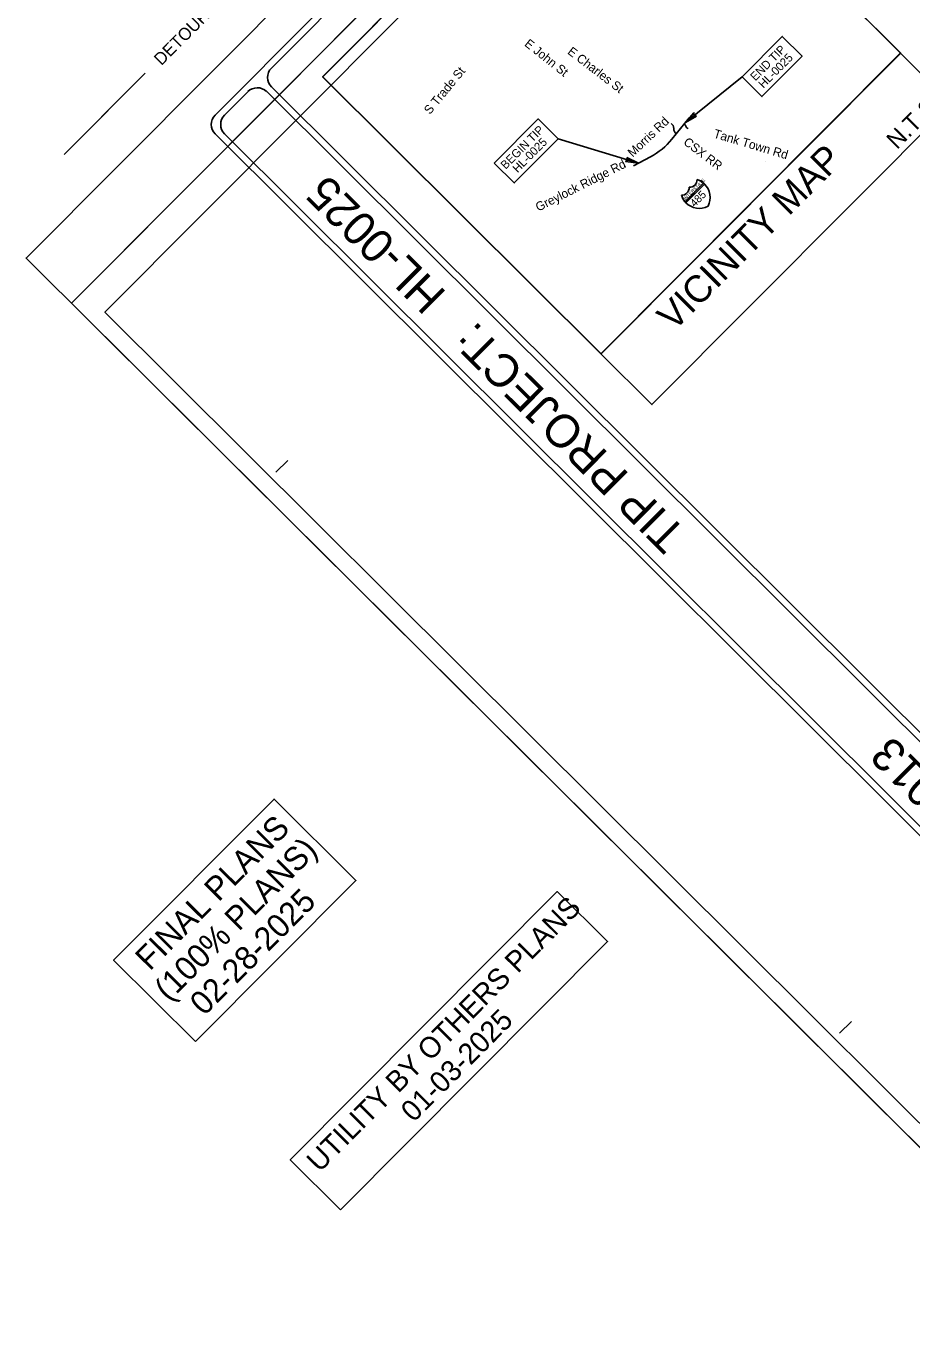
# Model space of a CAD drawing. Extents: x 1484850 to 1495577, y 495475 to 506245.
# Drawn here: x 1484916 to 1486921, y 495475 to 498431 of the extents above; entities that cross this region are included whole.
import ezdxf

# ---------------------------------------------------------------- set-up
doc = ezdxf.new("R2010")
doc.units = 0
for name, color, linetype in [('Cell Prop Down Guy _B', 7, 'Continuous'), ('Default', 7, 'Continuous'), ('Exist Utilities Gas UG Line SUE LOS B', 7, 'Continuous'), ('Exist Utilities Sanitary Sewer Manhole CELL', 7, 'Continuous'), ('Exist Utilities TV Pedestal CELL', 7, 'Continuous'), ('Exist Utilities TV UG Cable SUE LOS C', 7, 'Continuous'), ('Exist Utilities Water Meter CELL', 7, 'Continuous'), ('Exist Utilities Water UG Line SUE LOS C', 7, 'Continuous'), ('P Pole (Pow Co) CELL', 7, 'Continuous'), ('Prop Conduit _B', 7, 'Continuous'), ('Prop Guy Wire', 7, 'Continuous'), ('Prop UG Pow Cables', 7, 'Continuous')]:
    doc.layers.add(name, color=color, linetype=linetype)

msp = doc.modelspace()

# ---------------------------------------------------------------- linework, layer by layer
at = {"layer": 'Cell Prop Down Guy _B'}
for q in [(1488584.2, 501383.6), (1487357.7, 495475.3)]:
    msp.add_line((1485019.4, 497803.9), q, dxfattribs=at)
msp.add_lwpolyline([(1485019.4, 497803.9), (1488584.2, 501383.6), (1490922.5, 499055), (1487357.7, 495475.3)], close=True, dxfattribs=at)
at = {"layer": 'Default'}
for p, q in [((1485186.1, 498325), (1485018, 498156.3)), ((1485170.6, 498309.5), (1485002.6, 498140.8))]:
    msp.add_line(p, q, dxfattribs=at)
at = {"layer": 'Exist Utilities Gas UG Line SUE LOS B'}
for p, q in [((1486377.6, 498175.4), (1486416.8, 498224)), ((1486381.8, 498199.3), (1486381.8, 498199.9)), ((1486409.3, 498205.1), (1486410, 498203.6)), ((1486290.9, 498115.2), (1486329.2, 498135.5))]:
    msp.add_line(p, q, dxfattribs=at)
for centre, radius, start, end in [((1486366.2, 498199.2), 15.6, 2.8235, 50.7272), ((1486398.2, 498199.4), 16.4, 180.3319, 227.5042), ((1486397.2, 498200.3), 13, 21.6462, 49.5197), ((1486421.3, 498209.8), 12.9, 208.8639, 235.4773), ((1486256.3, 498273.1), 155.7, 297.895, 321.1156)]:
    msp.add_arc(centre, radius, start, end, dxfattribs=at)
at = {"layer": 'Exist Utilities Sanitary Sewer Manhole CELL'}
for points in [[(1486433.5, 498227.4), (1486408.1, 498213.2), (1486427.3, 498235.4), (1486427.7, 498229.1)], [(1486275.8, 498134.2), (1486301.8, 498121), (1486272.7, 498124.6), (1486277.7, 498128.4)]]:
    msp.add_lwpolyline(points, close=True, dxfattribs=at)
at = {"layer": 'Exist Utilities TV Pedestal CELL'}
for p, q in [((1486589.6, 498124.1), (1486589.5, 498124)), ((1486589.6, 498124.1), (1486589.5, 498124)), ((1486589.5, 498124), (1486589.6, 498124.1)), ((1486449.2, 498076), (1486407.2, 498033.8)), ((1486407.3, 498033.9), (1486449.2, 498076)), ((1486451.5, 498073.9), (1486409.3, 498031.5)), ((1486409.3, 498031.5), (1486451.5, 498073.9))]:
    msp.add_line(p, q, dxfattribs=at)
for centre, radius, start, end in [((1486417.6, 498083.3), 16.8, 266.268, 2.8189), ((1486421.9, 498043.6), 42.4, 49.933, 72.9434), ((1486399.7, 498065.4), 16.8, 267.4184, 3.9692), ((1486421.9, 498043.6), 42.4, 45.6712, 49.9313), ((1486421.9, 498043.6), 42.4, 332.3215, 45.6591), ((1486439.5, 498061.2), 42.4, 197.294, 220.283), ((1486439.5, 498061.2), 42.4, 220.3043, 224.5656), ((1486439.5, 498061.3), 42.4, 224.5841, 297.9157)]:
    msp.add_arc(centre, radius, start, end, dxfattribs=at)
at = {"layer": 'Exist Utilities TV UG Cable SUE LOS C'}
for points in [[(1486536.3, 498316.9), (1486627.2, 498408.3), (1486672.2, 498363.5), (1486581.2, 498272.1)], [(1485975.8, 498121.4), (1486075.3, 498221.3), (1486120.3, 498176.5), (1486020.8, 498076.6)]]:
    msp.add_lwpolyline(points, close=True, dxfattribs=at)
at = {"layer": 'Exist Utilities Water Meter CELL'}
for p, q in [((1486536.3, 498316.9), (1486408.1, 498213.2)), ((1486120.1, 498176.6), (1486301.8, 498121))]:
    msp.add_line(p, q, dxfattribs=at)
msp.add_lwpolyline([(1486217.1, 497689.6), (1486895.2, 498370.5), (1487010.5, 498255.7), (1486332.4, 497574.8)], close=True, dxfattribs=at)
at = {"layer": 'Exist Utilities Water UG Line SUE LOS C'}
for points in [[(1486441.9, 498821.9), (1486895.2, 498370.5), (1486217.1, 497689.6), (1485587.2, 498316.9), (1486082.4, 498814.2), (1486259, 498638.3)], [(1486441.9, 498821.9), (1486895.4, 498370.4), (1486217.3, 497689.5), (1485587.4, 498316.8), (1486082.5, 498814.1), (1486259, 498638.3)]]:
    msp.add_lwpolyline(points, close=True, dxfattribs=at)
at = {"layer": 'P Pole (Pow Co) CELL'}
msp.add_lwpolyline([(1488481.3, 501486.1), (1484916.4, 497906.4), (1487254.7, 495577.9), (1490819.6, 499157.6)], close=True, dxfattribs=at)
at = {"layer": 'Prop Conduit _B'}
for points in [[(1485299.3, 496132.4), (1485114.2, 496316.7), (1485477.4, 496681.4), (1485662.5, 496497.1)], [(1485627.6, 495752), (1485513.9, 495865.2), (1486118.3, 496472.1), (1486232, 496358.9)]]:
    msp.add_lwpolyline(points, close=True, dxfattribs=at)
at = {"layer": 'Prop Guy Wire'}
msp.add_lwpolyline([(1487337.5, 495550.5), (1490865.3, 499093), (1488622.4, 501326.5), (1485094.6, 497784)], close=True, dxfattribs=at)
at = {"layer": 'Prop UG Pow Cables'}
for p, q in [((1487246.4, 496526.1), (1485471.4, 498293.7)), ((1487629, 496123.8), (1485460.8, 498283.1)), ((1485481.7, 497421.8), (1485508.2, 497448.4)), ((1485481.7, 497421.8), (1485508.2, 497448.4)), ((1486757.1, 496151.7), (1486783.6, 496178.3)), ((1486757.1, 496151.7), (1486783.6, 496178.3))]:
    msp.add_line(p, q, dxfattribs=at)
for points in [[(1488477.3, 501375.9), (1485344.2, 498229.8)], [(1488477.3, 501354.6), (1485471.3, 498336.1)], [(1485418.4, 498282.9), (1485365.4, 498229.8)], [(1485344.3, 498187.4), (1487533.8, 496006.9)], [(1485344.3, 498187.4), (1487533.8, 496006.9)], [(1485365.6, 498187.4), (1487533.8, 496028.2)]]:
    msp.add_lwpolyline(points, dxfattribs=at)
for points in [[(1486895.2, 498370.5), (1486217.1, 497689.6), (1485587.2, 498316.9), (1486265.2, 498997.8)], [(1485587.2, 498316.9), (1486082.4, 498814.2), (1486259, 498638.3), (1486441.9, 498821.9), (1486895, 498370.6), (1486217, 497689.7)], [(1486217.1, 497689.6), (1486895.2, 498370.5), (1487010.5, 498255.7), (1486332.4, 497574.8)]]:
    msp.add_lwpolyline(points, close=True, dxfattribs=at)
for centre, start, end in [((1485492.5, 498315), 135.1191, 225.1191), ((1485439.5, 498261.9), 45.1191, 135.1191), ((1485365.4, 498208.7), 135.1191, 225.1191), ((1485386.6, 498208.8), 135.1191, 225.1191)]:
    msp.add_arc(centre, 30, start, end, dxfattribs=at)

# ---------------------------------------------------------------- texts
at = {"layer": 'Default'}
for s, rotation, p in [('E John St', 321.3901, (1486042.4, 498388.4)), ('E Charles St', 322.4571, (1486139.8, 498370.3)), ('S Trade St', 50.5492, (1485830.1, 498230.1)), ('Morris Rd', 43.598, (1486288.9, 498133.7)), ('Tank Town Rd', 343.3292, (1486470.3, 498179.6)), ('CSX RR', 322.4571, (1486402, 498165.5)), ('Greylock Ridge Rd', 26.8476, (1486075.3, 498011.3))]:
    msp.add_text(s, height=20, rotation=rotation, dxfattribs=at).set_placement(p)
at = {"layer": 'Exist Utilities TV Pedestal CELL'}
for s, height, p in [('INTERSTATE', 7.5, (1486407.9, 498036.7)), ('485', 17.47, (1486429.2, 498020.8))]:
    msp.add_text(s, height=height, rotation=45.1186, dxfattribs=at).set_placement(p)
at = {"layer": 'Exist Utilities Water Meter CELL'}
for s, height, rotation, p in [('DETOUR ROUTE', 28, 45.1191, (1485222.5, 498340.7)), ('END TIP', 18.93, 45.1327, (1486566.2, 498306.1)), ('HL-0025', 18.93, 45.1327, (1486584.6, 498289.5)), ('N.T.S.', 39.2, 45.1191, (1486886.8, 498150.5)), ('BEGIN TIP', 18.93, 45.1327, (1486001.4, 498106.2)), ('HL-0025', 18.93, 45.1327, (1486028.4, 498098.2)), ('VICINITY MAP', 61.25, 45.1191, (1486381.9, 497738.5))]:
    msp.add_text(s, height=height, rotation=rotation, dxfattribs=at).set_placement(p)
at = {"layer": 'Prop Conduit _B'}
for s, height, rotation, p in [('FINAL PLANS', 53.058, 45.1149, (1485196.1, 496290.8)), ('(100% PLANS)', 53.058, 45.1149, (1485239.2, 496221.3)), ('02-28-2025', 53.06, 45.1149, (1485319.3, 496189)), ('UTILITY BY OTHERS PLANS', 47.263, 45.1191, (1485580.1, 495834.7)), ('01-03-2025', 47.26, 45.1191, (1485793.1, 495948.1))]:
    msp.add_text(s, height=height, rotation=rotation, dxfattribs=at).set_placement(p)
at = {"layer": 'Prop UG Pow Cables'}
for s, p in [('HL-0025', (1485870.2, 497827.1)), ('TIP PROJECT:', (1486413.5, 497286.1)), ('C205013', (1487162.7, 496540))]:
    msp.add_text(s, height=75, rotation=135.1191, dxfattribs=at).set_placement(p)

doc.saveas('drawing.dxf')
